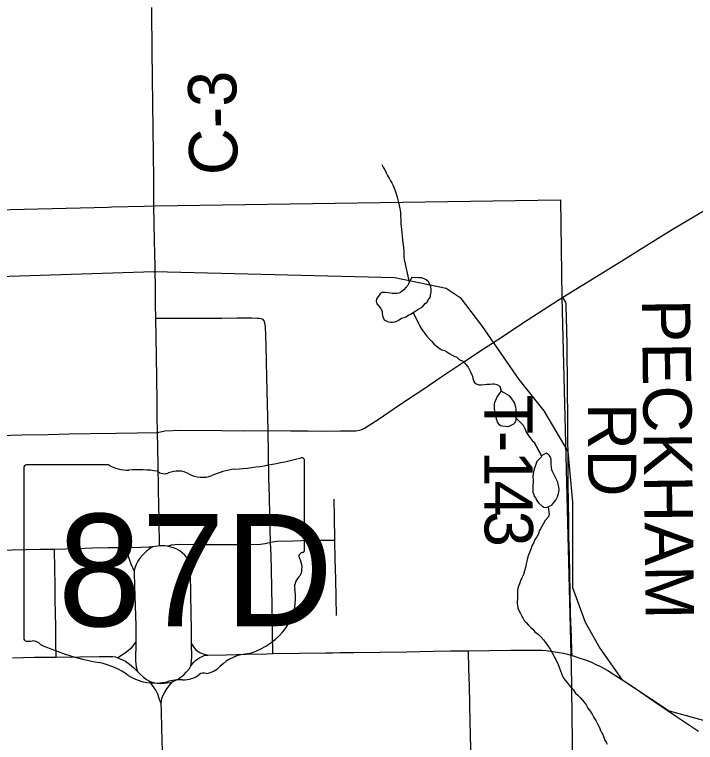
# Model space of a CAD drawing. Extents: x 103424 to 290657, y 38711 to 110967.
# Drawn here: x 160839 to 165088, y 60374 to 64911 of the extents above; entities that cross this region are included whole.
import ezdxf

# ---------------------------------------------------------------- set-up
doc = ezdxf.new("R2010")
doc.units = 0
for name, color, linetype in [('GM_X_City_Street', 7, 'Continuous'), ('GM_X_Corporation', 7, 'Continuous'), ('GM_X_County_Road', 7, 'Continuous'), ('GM_X_County_Road_Text', 7, 'Continuous'), ('GM_X_Minor_Lake', 7, 'Continuous'), ('GM_X_Minor_River', 7, 'Continuous'), ('GM_X_Rail_Line', 7, 'Continuous'), ('GM_X_State_Location', 7, 'Continuous'), ('GM_X_State_Route', 7, 'Continuous'), ('GM_X_State_Shield', 7, 'Continuous'), ('GM_X_Township_Road', 7, 'Continuous'), ('GM_X_Township_Road_Text', 7, 'Continuous')]:
    doc.layers.add(name, color=color, linetype=linetype)

msp = doc.modelspace()

# ---------------------------------------------------------------- linework, layer by layer
at = {"layer": 'GM_X_City_Street'}
for points in [[(161731.1, 62306.2), (161777, 62316.9), (161875.5, 62320.1), (162131.9, 62317.8), (162277.1, 62316.5), (162421.5, 62318), (162560.4, 62317), (162669.7, 62316), (162779.1, 62314.9), (162875.5, 62316), (162971.8, 62317), (162989.9, 62320.1), (163006, 62324.8), (163022.1, 62332.5), (163113.8, 62390.6), (163202.5, 62450.9), (163291.1, 62511.1), (163392.1, 62578.1), (163499.3, 62650.2), (163574.4, 62700.4), (163649.5, 62750.7), (163765.1, 62826.4), (163880.7, 62902.3), (164008.9, 62986.6), (164137, 63070.9), (164260.6, 63148.3)], [(161720.8, 63018.2), (161967.9, 63017.5), (162133, 63018.8), (162226, 63019.5), (162319, 63020.2), (162352.9, 63019.3), (162366.5, 63017.8), (162378.6, 63015.8), (162389.5, 63011.4)], [(162451.3, 60927.5), (162448.8, 61057.2), (162446.1, 61222.2), (162444.2, 61336.9), (162442.3, 61451.5), (162439.5, 61537.2), (162436.7, 61623), (162432.3, 61788), (162429.1, 61905.1), (162426, 62022.1), (162423.7, 62170.1), (162421.5, 62318), (162420, 62400.7), (162418.5, 62483.4), (162414.1, 62648.4), (162411.5, 62749.1), (162408.9, 62849.9), (162404.6, 62966.8), (162403.4, 62976.7), (162401.5, 62987.5), (162396.8, 63001.1), (162389.5, 63011.4)], [(160449, 62278), (160614, 62282.7), (160749.4, 62286.5), (160884.6, 62290.3), (161049.7, 62293.8), (161180.4, 62296.7), (161311.2, 62299.5), (161476.2, 62302.1), (161603.7, 62304.1), (161731.1, 62306.2)], [(162847.6, 61164.1), (162845.3, 61277.7), (162842.9, 61391.4), (162839.8, 61513.4), (162836.8, 61635.4), (162834.9, 61781.4), (162833.5, 61889.3)], [(161960.3, 61607.8), (162013, 61607.4), (162129.9, 61606.7), (162252, 61608.5), (162374.1, 61610.3), (162402.1, 61613.9), (162436.7, 61623)], [(162436.7, 61623), (162475.3, 61627.6), (162577.1, 61631), (162678.8, 61634.3), (162836.8, 61635.4)], [(160461.2, 61566.9), (160571.8, 61570), (160736.9, 61573), (160824.3, 61574.6), (160911.6, 61576.1), (160999.8, 61577.7), (161087.9, 61579.3), (161228.5, 61583.3), (161325.5, 61586.1), (161422.5, 61588.8), (161535.7, 61589.4)], [(161098.6, 60904.2), (161097.8, 61000.5), (161096.9, 61096.9), (161093.8, 61261.9), (161092, 61357.8), (161090.2, 61453.6), (161087.9, 61579.3)], [(161535.7, 61589.4), (161626.7, 61590.6), (161676.3, 61592.3), (161700.6, 61592.1)], [(161586.7, 61443.3), (161566.6, 61484.1), (161555.9, 61515), (161544, 61553.1), (161535.7, 61589.4)], [(161792.7, 61597.2), (161805.7, 61601.9), (161819.1, 61604.8), (161840.7, 61606.6), (161874.4, 61608.6), (161960.3, 61607.8)], [(161932.3, 61477.4), (161939.2, 61509.5), (161947.5, 61547.9), (161955.3, 61584.4), (161960.3, 61607.8)], [(163706.8, 59642.2), (163701.4, 59807.1), (163698.4, 59899.4), (163695.3, 59991.6), (163691.2, 60156.6), (163689, 60247.1), (163686.8, 60337.6), (163682.8, 60502.6), (163680.1, 60613.5), (163677.4, 60724.4), (163674.3, 60835), (163671.2, 60945.6)]]:
    msp.add_lwpolyline(points, dxfattribs=at)
at = {"layer": 'GM_X_Corporation'}
msp.add_lwpolyline([(160200.3, 63681.5), (161423.7, 63710.9), (161447.1, 63711.5), (161648, 63716.6), (161715.5, 63717.6), (164245, 63755), (164253, 63145.7), (164310.7, 60921.1), (164311.2, 60868.6), (164320.2, 60217.4), (164333, 59263.8), (164346.8, 58251.2), (162688.5, 58208.3), (161804.4, 58185.4), (161771.2, 58184.7), (160501.7, 58157)], dxfattribs=at)
at = {"layer": 'GM_X_County_Road'}
msp.add_line((161709.4, 63714.6), (161708.4, 63805.1), dxfattribs=at)
for points in [[(161708.4, 63805.1), (161707.7, 63879.7), (161705.9, 64044.7), (161704.4, 64198.9), (161702.7, 64353.1), (161700.6, 64518.1), (161698.5, 64683.2), (161697.4, 64767.4), (161696.3, 64851.7), (161695.5, 64955.1)], [(161733.1, 62198.3), (161732.9, 62209.1), (161731.1, 62306.2), (161729.8, 62404.9), (161728.6, 62503.6), (161727, 62642.7), (161725.4, 62781.8), (161723.1, 62900), (161720.8, 63018.2), (161719.7, 63100.8), (161718.7, 63183.5), (161716.1, 63342.3), (161713.5, 63501.1), (161711.4, 63607.8), (161709.4, 63714.6)], [(164260.6, 63148.3), (164379.4, 63221.9), (164498.1, 63295.6), (164638.3, 63382.8), (164778.5, 63469.9), (164855.5, 63517.8), (164932.5, 63565.6), (165074.8, 63649.2), (165217.1, 63732.8)], [(161744.6, 61598.4), (161741.4, 61762.1), (161739.6, 61854.5), (161737.9, 61947), (161734.8, 62112.1), (161733.1, 62198.3)]]:
    msp.add_lwpolyline(points, dxfattribs=at)
at = {"layer": 'GM_X_Minor_Lake'}
for points in [[(163317.9, 63271.7), (163302.3, 63243.1), (163292.6, 63222.7), (163282.7, 63212.4), (163268.9, 63195.9), (163257, 63185.6), (163247.1, 63179.3), (163237, 63175), (163225, 63172.8), (163208.8, 63172.4), (163194.7, 63172.1), (163184.5, 63173.9), (163168.3, 63175.6), (163154.1, 63177.3), (163144, 63179.1), (163133.9, 63178.9), (163121.9, 63174.6), (163114, 63162.3), (163104.2, 63147.9), (163098.4, 63137.7), (163096.6, 63125.6), (163099, 63107.4), (163113.5, 63091.6), (163124, 63075.7), (163132.3, 63061.7), (163132.6, 63049.6), (163135, 63033.5), (163145.6, 63007.5), (163166, 62997.8), (163182.3, 62994.1), (163198.5, 62992.5), (163212.6, 62994.8), (163224.6, 62999.1), (163238.6, 63007.5), (163254.5, 63017.9), (163270.6, 63022.3), (163280.6, 63026.6), (163296.6, 63037), (163310.6, 63043.4), (163326.5, 63053.8), (163342.5, 63064.3), (163356.5, 63072.6), (163370.4, 63081), (163384.4, 63089.4), (163402.1, 63110), (163412.1, 63116.2), (163421.8, 63134.6), (163433.6, 63151), (163435.4, 63161.2), (163437.2, 63171.3), (163439, 63183.4), (163438.6, 63199.6), (163436.3, 63213.7), (163429.9, 63229.7), (163421.5, 63245.7), (163407.1, 63257.5), (163394.8, 63263.3), (163378.5, 63269), (163360.8, 63269.8)], [(163360.8, 63269.8), (163317.9, 63271.7)], [(163876.3, 62562.6), (163864.8, 62550.6), (163856.9, 62538.3), (163849.1, 62526), (163843.3, 62515.8), (163835.6, 62497.5), (163831.8, 62483.3), (163832.1, 62469.1), (163832.5, 62451), (163839.5, 62410.7), (163841.7, 62400.7), (163843.9, 62390.6), (163848.2, 62380.6), (163850.4, 62370.6), (163858.7, 62360.7), (163871.1, 62348.8), (163881.2, 62347), (163901.5, 62345.5), (163913.6, 62343.7)], [(163876.3, 62562.6), (163864.8, 62550.6), (163856.9, 62538.3), (163849.1, 62526), (163843.3, 62515.8), (163835.6, 62497.5), (163831.8, 62483.3), (163832.1, 62469.1), (163832.5, 62451), (163839.5, 62410.7), (163841.7, 62400.7), (163843.9, 62390.6), (163848.2, 62380.6), (163850.4, 62370.6), (163858.7, 62360.7), (163871.1, 62348.8), (163881.2, 62347), (163901.5, 62345.5), (163913.6, 62343.7), (163925.7, 62346), (163941.7, 62352.4), (163953.7, 62358.7), (163963.6, 62369), (163969.3, 62385.3), (163969.1, 62395.4), (163968.8, 62409.5), (163968.6, 62421.6), (163968.3, 62435.7), (163968, 62449.9), (163967.7, 62462), (163963.3, 62480.1), (163959, 62490.1), (163952.8, 62500), (163946.5, 62510), (163940.2, 62519.9), (163927.8, 62533.8), (163876.3, 62562.6)], [(163913.6, 62343.7), (163925.7, 62346), (163941.7, 62352.4), (163953.7, 62358.7), (163963.6, 62369), (163969.3, 62385.3), (163969.1, 62395.4), (163968.8, 62409.5), (163968.6, 62421.6), (163968.3, 62435.7), (163968, 62449.9), (163967.7, 62462), (163963.3, 62480.1), (163959, 62490.1), (163952.8, 62500), (163946.5, 62510), (163940.2, 62519.9), (163927.8, 62533.8), (163876.3, 62562.6)], [(164127.7, 62160.6), (164125.9, 62152.4), (164112, 62140), (164098.2, 62125.6), (164079.1, 62070.7), (164075.5, 62048.4), (164073.9, 62030.2), (164074.3, 62010), (164074.7, 61993.8), (164073, 61979.7), (164073.2, 61969.6), (164073.5, 61953.4), (164073.7, 61943.3), (164074, 61933.3), (164078.3, 61919.2), (164080.5, 61909.2), (164090.9, 61897.3), (164093.1, 61887.2), (164101.5, 61875.3), (164109.7, 61865.4), (164128.3, 61847.6), (164142.6, 61839.8), (164152.8, 61838), (164168.9, 61842.4), (164180.8, 61848.7), (164190.9, 61853), (164204.7, 61869.5), (164216.5, 61883.8), (164222.3, 61896.1), (164228.1, 61908.3), (164231.9, 61918.5), (164235.7, 61932.7), (164237.2, 61953), (164235, 61965), (164230.5, 61983.1), (164228.3, 61995.2), (164217.7, 62017.1), (164207.2, 62037.1), (164196.5, 62063.1), (164192.2, 62073.1), (164189.9, 62087.2), (164187.5, 62107.3), (164186.8, 62137.6), (164184.6, 62147.7), (164174.1, 62163.6), (164161.8, 62173.4), (164155.7, 62177.3), (164127.7, 62160.6)], [(164127.7, 62160.6), (164125.9, 62152.4), (164112, 62140), (164098.2, 62125.6), (164079.1, 62070.7), (164075.5, 62048.4), (164073.9, 62030.2), (164074.3, 62010), (164074.7, 61993.8), (164073, 61979.7), (164073.2, 61969.6), (164073.5, 61953.4), (164073.7, 61943.3), (164074, 61933.3), (164078.3, 61919.2), (164080.5, 61909.2), (164090.9, 61897.3), (164093.1, 61887.2), (164101.5, 61875.3), (164109.7, 61865.4), (164128.3, 61847.6), (164142.6, 61839.8), (164152.8, 61838), (164168.9, 61842.4)], [(164168.9, 61842.4), (164180.8, 61848.7), (164190.9, 61853), (164204.7, 61869.5), (164216.5, 61883.8), (164222.3, 61896.1), (164228.1, 61908.3), (164231.9, 61918.5), (164235.7, 61932.7), (164237.2, 61953), (164235, 61965), (164230.5, 61983.1), (164228.3, 61995.2), (164217.7, 62017.1), (164207.2, 62037.1), (164196.5, 62063.1), (164192.2, 62073.1), (164189.9, 62087.2), (164187.5, 62107.3), (164186.8, 62137.6), (164184.6, 62147.7), (164174.1, 62163.6), (164161.8, 62173.4), (164155.7, 62177.3), (164127.7, 62160.6)]]:
    msp.add_lwpolyline(points, dxfattribs=at)
at = {"layer": 'GM_X_Minor_River'}
for points in [[(163131.8, 63975.7), (163135.3, 63968.4), (163141.6, 63956.4), (163150, 63942.4), (163158.4, 63924.4), (163166.9, 63908.5), (163177.4, 63890.5), (163185.8, 63874.6), (163194.1, 63862.6), (163200.5, 63848.6), (163204.8, 63834.6), (163213.4, 63812.6), (163219.9, 63792.5), (163226.4, 63772.5), (163230.7, 63756.4), (163235.2, 63738.3), (163239.6, 63720.3), (163244, 63702.2), (163246.6, 63678), (163247, 63655.8), (163249.6, 63631.6), (163250.1, 63605.4), (163252.9, 63571.1), (163255.3, 63551), (163257.8, 63528.8), (163260.3, 63506.7), (163262.6, 63492.6), (163265.4, 63456.3), (163267.9, 63436.2), (163268.2, 63420), (163268.6, 63401.9), (163271.1, 63381.7), (163273.4, 63367.6), (163275.5, 63363.6), (163275.5, 63361.6), (163275.7, 63355.6), (163302.3, 63243.1)], [(163326.5, 63053.8), (163370.9, 62963.9), (163381.3, 62948), (163389.6, 62938.1), (163395.9, 62928.1), (163404.2, 62916.2), (163412.5, 62906.3), (163429.1, 62888.4), (163441.5, 62874.6), (163456, 62858.7), (163470.4, 62844.9), (163488.9, 62831.2), (163505.3, 62821.5), (163521.5, 62817.8), (163535.9, 62808), (163554.3, 62796.3), (163574.8, 62786.6), (163587, 62778.8), (163597.2, 62777), (163609.6, 62765.2), (163621.9, 62757.3), (163634.1, 62751.6), (163646.5, 62739.7), (163656.9, 62727.8), (163669.3, 62711.9), (163677.7, 62696), (163686.2, 62680), (163692.5, 62666), (163696.8, 62656), (163699.1, 62641.9), (163705.6, 62623.9), (163713.9, 62611.9), (163738.4, 62602.4), (163752.5, 62602.7), (163770.6, 62605.1), (163786.7, 62607.5), (163796.8, 62607.7), (163807, 62607.9), (163821.1, 62608.2), (163831.2, 62608.4), (163847.4, 62604.8), (163863.8, 62597), (163867.9, 62595.1), (163876.3, 62562.6)], [(163969.1, 62395.4), (164012.5, 62351.9), (164018.9, 62337.9), (164025.2, 62325.9), (164033.7, 62303.9), (164042, 62294), (164048.3, 62282), (164056.6, 62272.1), (164069.1, 62256.2), (164081.5, 62244.4), (164127.7, 62160.6), (164081.5, 62244.4)], [(164168.9, 61842.4), (164173.9, 61794.1), (164168.2, 61777.8), (164150.5, 61757.2), (164121.2, 61706.1), (164113.4, 61691.8), (164107.8, 61673.5), (164098.1, 61655.1), (164086.3, 61638.7), (164078.6, 61620.4), (164068.8, 61604), (164063.2, 61583.7), (164053.6, 61561.3), (164045.9, 61542.9), (164040.2, 61522.6), (164034.6, 61504.3), (164030.9, 61486.1), (164027.3, 61463.8), (164021.7, 61443.5), (164014.1, 61421.1), (164004.4, 61400.7), (163996.8, 61380.4), (163989.1, 61362), (163983.3, 61347.8), (163979.6, 61333.5), (163977.9, 61319.4), (163978.1, 61309.3), (163978.3, 61299.2), (163976.5, 61287), (163976.9, 61268.9), (163975.3, 61250.7), (163975.5, 61238.6), (163977.8, 61228.5), (163980.2, 61212.4), (163984.4, 61202.4), (163990.8, 61188.4), (163995.1, 61176.4), (164001.4, 61164.4), (164009.8, 61150.5), (164018.2, 61134.5), (164030.6, 61120.6), (164045.1, 61104.8), (164059.5, 61091), (164073.9, 61079.2), (164086.4, 61063.3), (164106.9, 61047.6), (164123.5, 61031.8), (164140, 61014), (164152.5, 60996.1), (164167.1, 60976.2), (164181.7, 60954.3), (164194.3, 60932.4), (164223.7, 60878.5), (164230.2, 60860.5), (164238.8, 60836.4), (164245.2, 60820.4), (164251.6, 60802.4), (164258, 60786.3), (164266.4, 60772.4), (164274.7, 60762.5), (164283, 60750.5), (164291.3, 60740.6), (164301.7, 60728.7), (164314.1, 60714.9), (164326.5, 60701), (164339.1, 60681.1), (164355.6, 60667.3), (164368, 60653.5), (164380.4, 60639.6), (164392.9, 60623.7), (164405.3, 60607.8), (164415.9, 60587.8), (164430.4, 60568), (164442.9, 60550.1), (164453.5, 60530.1), (164466, 60510.2), (164476.6, 60490.2), (164489.2, 60466.3), (164495.6, 60448.2), (164501.9, 60436.3), (164508.2, 60426.3), (164514.6, 60410.3), (164518.9, 60400.3), (164523.2, 60388.3), (164529.5, 60376.3), (164535.9, 60362.3)]]:
    msp.add_lwpolyline(points, dxfattribs=at)
at = {"layer": 'GM_X_Rail_Line'}
msp.add_lwpolyline([(160415.4, 63267.2), (161709.6, 63308.7), (163212.6, 63271.3), (163532.3, 63204.9), (163619.5, 63146.7), (163752.3, 62972.3), (163984.8, 62635.9), (164142.6, 62440.7), (164292.1, 62187.3), (164321.1, 61871.7), (164321.1, 61340), (164400, 61124.1), (164491.4, 60962.1), (164628.4, 60766.9), (164923.1, 60571.7), (165172.3, 60501.1)], dxfattribs=at)
at = {"layer": 'GM_X_State_Route'}
for points in [[(161744.6, 61598.4), (161732.9, 61597.6), (161717.5, 61595.6), (161700.6, 61592.1), (161681.7, 61580.4), (161663.5, 61565.2), (161654.1, 61556.8), (161641.1, 61544.4), (161624.2, 61523.8), (161609.5, 61502.9), (161597.5, 61483), (161589.2, 61459.4), (161586.7, 61443.3), (161585.5, 61435.9), (161587, 61347), (161591.9, 61224.8), (161596.9, 61102.5), (161596.9, 61000.9), (161595, 60881.6), (161598.7, 60845.8), (161605.5, 60816.6)], [(161940.2, 60851), (161943.8, 60879.9), (161945.5, 60907.2), (161944.3, 60987.6), (161943, 61081.2), (161941.8, 61174.8), (161939.6, 61300.5), (161937.4, 61426.1), (161936.2, 61450.7), (161932.3, 61477.4), (161926.9, 61495.8), (161921, 61511.6), (161911.6, 61528), (161901.1, 61540.9), (161888.2, 61553.2), (161869.9, 61568.4), (161851.2, 61579.1), (161830.7, 61586.6), (161813.9, 61591.4), (161792.7, 61597.2), (161777, 61598.9), (161744.6, 61598.4)], [(161596.9, 61000.9), (161582.5, 60981.2), (161564.4, 60960.2), (161539.1, 60938.1), (161506, 60915), (161484.5, 60900.7)], [(161944.3, 60987.6), (161960.1, 60962.6), (161970.8, 60950.8), (161984, 60940.3), (161996.3, 60933.7), (162009.9, 60928.5), (162023.6, 60924.9), (162045.8, 60917.7)], [(162822.7, 60932.9), (162869.1, 60933.6), (162956.8, 60934.9), (163121.5, 60936.2), (163286.5, 60939), (163451.5, 60941.9), (163561.4, 60943.7), (163671.2, 60945.6), (163803.1, 60947), (163935, 60948.3), (164051.9, 60949.8), (164104.9, 60949.2), (164130.8, 60948), (164157.2, 60945.8), (164185.1, 60942.7), (164212, 60938.9), (164237.3, 60934.6), (164264.2, 60929.2), (164289.8, 60923), (164317.4, 60916.1)], [(160826.9, 60900.1), (160964.4, 60904.2), (161098.6, 60904.2), (161247.5, 60907.9), (161367.2, 60909), (161420.1, 60909.8), (161451.8, 60909), (161468.9, 60906.9), (161484.5, 60900.7), (161503.2, 60893.2), (161531.7, 60879.7), (161557.5, 60861.6), (161581.5, 60841.2), (161605.5, 60816.6)], [(161940.2, 60851), (161956.9, 60872.5), (161967.9, 60884.8), (161982.5, 60895.6), (161994.6, 60903), (162006.4, 60908.3), (162023.1, 60914.8), (162045.8, 60917.7)], [(162045.8, 60917.7), (162159.5, 60920.6), (162286.9, 60923.6), (162414.3, 60926.7), (162451.3, 60927.5), (162616.3, 60929.9), (162781.4, 60932.3), (162822.7, 60932.9)], [(164317.4, 60916.1), (164343.6, 60907.8), (164367.1, 60899.8), (164392.8, 60891), (164417.9, 60881.5), (164443, 60871.6), (164466.8, 60860.3), (164491.4, 60848.4), (164540.2, 60821.5), (164583.5, 60795.9), (164692.1, 60723.8), (164828.8, 60631.4), (164899.2, 60583.9), (164969.5, 60536.4), (165106, 60443.5)], [(161680.6, 60756), (161704, 60747.2), (161727.1, 60743.1), (161749.5, 60741.8), (161791.8, 60744.2), (161807.6, 60747.3), (161824.5, 60751.9), (161841.3, 60759), (161860.3, 60769), (161878.8, 60782), (161894.6, 60794.7), (161910.8, 60811.4), (161930.1, 60835.1), (161940.2, 60851)], [(161605.5, 60816.6), (161625.2, 60797.2), (161643.2, 60781.4), (161661.8, 60766.6), (161680.6, 60756)], [(161753.5, 60613.7), (161742.6, 60648), (161733.1, 60674.7), (161720, 60699.5), (161710.9, 60713.5), (161680.6, 60756)], [(161753.5, 60613.7), (161759.1, 60647.7), (161766.7, 60668.4), (161776.4, 60687.8), (161790.1, 60707.3), (161804.1, 60727.1), (161824.5, 60751.9)], [(161784.8, 59525.7), (161782.9, 59592.3), (161781.2, 59651), (161779.4, 59717.8), (161777.9, 59772.6), (161775.7, 59826.2), (161773.7, 59922.2), (161771.2, 60015.7), (161769.6, 60073.1), (161767.3, 60157.2), (161765.5, 60222.1), (161762.9, 60314.2), (161760.8, 60391.7), (161758.9, 60459.1), (161755.3, 60571.3), (161753.5, 60613.7)]]:
    msp.add_lwpolyline(points, dxfattribs=at)
at = {"layer": 'GM_X_State_Shield'}
for p, q in [((162648.3, 61574.8), (162648.3, 62131)), ((160897.3, 62086.4), (160897.3, 61023.1)), ((161427.3, 62104.7), (160914.5, 62104.7)), ((162648.2, 61574.9), (162648.3, 61574.8))]:
    msp.add_line(p, q, dxfattribs=at)
for centre, major_axis, start_param, end_param in [((162024.6, 63554.2), (1857, 0), 4.814394, 5.042369), ((162628.9, 62133.3), (19.5, 0), 6.141152, 7.989035), ((160917.3, 62088.6), (20.3, 0), 1.712693, 3.28349), ((161549.4, 62228.1), (196.8, 0), 4.042523, 4.731795), ((161614.7, 61507.7), (706.4, 0), 1.404758, 1.657858), ((161858.4, 61971.2), (118, 0), 0.950623, 2.079405), ((162261.4, 61779.9), (373.6, 0), 1.699011, 2.107814), ((161775, 62094.1), (56.8, 0), 3.836095, 5.185415), ((162010.7, 62139.8), (142, 0), 4.081561, 5.145723), ((162627.5, 61572.7), (20.9, 0), 5.05454, 6.418171), ((162643.8, 61534), (30.2, 0), 1.883978, 3.671073), ((162451.9, 61463.7), (181.1, 0), 5.934695, 6.695948), ((162718.2, 61342.1), (131.8, 0), 2.387724, 3.262537), ((162128.6, 61271.3), (464.5, 0), 5.101752, 6.440018), ((160917.5, 61020.8), (20.5, 0), 3.00124, 4.508301), ((160920.6, 61129.6), (156.2, 0), 4.665946, 4.897461), ((160952.6, 60961.8), (56.3, 0), 0.519207, 1.627899), ((161663.6, 61917.1), (1341, 0), 4.195997, 4.488961), ((162324.5, 60724.6), (254.4, 0), 1.647645, 2.488434), ((161263.8, 60545.5), (419.6, 0), 0.823519, 1.323587), ((162002.2, 60920.1), (150.1, 0), 4.937069, 5.64225), ((162019.2, 60773.9), (39.9, 0), 1.147584, 2.315152), ((161717.6, 60956.5), (266.2, 0), 4.026481, 4.996735), ((161871.4, 60588.9), (218.8, 0), 1.495662, 1.94098), ((161890.9, 60876.9), (141.9, 0), 4.691044, 5.507374)]:
    msp.add_ellipse(centre, major_axis=major_axis, ratio=0.8, start_param=start_param, end_param=end_param, dxfattribs=at)
at = {"layer": 'GM_X_Township_Road'}
msp.add_lwpolyline([(164317.4, 60916.1), (164316.7, 60942.1), (164313.4, 61034.3), (164310.1, 61126.5), (164308.2, 61179.9), (164306.3, 61305.3), (164304.5, 61430.7), (164301.3, 61541.6), (164298.2, 61652.6), (164296.8, 61751.7), (164295.1, 61868.7), (164293.3, 61985.7), (164292.4, 62150.7), (164291.7, 62277.1), (164291, 62403.4), (164289.5, 62568.5), (164288.6, 62667), (164287.7, 62765.6), (164286.9, 62854.9), (164286.1, 62944.3), (164281.8, 63095.4), (164280, 63107.5), (164276.2, 63119.1), (164271.1, 63130.4), (164260.6, 63148.3)], dxfattribs=at)

# ---------------------------------------------------------------- texts
at = {"layer": 'GM_X_County_Road_Text'}
msp.add_text('C-3', height=301.87, rotation=90.9075, dxfattribs=at).set_placement((162232.2, 63912.1))
at = {"layer": 'GM_X_State_Location'}
for s in ['s', 'r']:
    msp.add_text(s, height=1.01, dxfattribs=at).set_placement((161753.1, 61484.1))
msp.add_text('87D', height=1.01, rotation=0, dxfattribs=at).set_placement((161366.9, 61410.9))
at = {"layer": 'GM_X_State_Shield'}
msp.add_text('87D', height=700.44, dxfattribs=at).set_placement((161109.3, 61098.1))
at = {"layer": 'GM_X_Township_Road_Text'}
for s, height, rotation, p in [('PECKHAM', 301.87, 270.7005, (164753.2, 63135.6)), ('T', 301.9, 270, (163769.5, 62542.8)), ('RD', 301.87, 270, (164416.5, 62489.6)), ('-', 301.9, 270.0071, (163769.5, 62316.9)), ('1', 301.9, 270.0502, (163769.5, 62192.7)), ('4', 301.9, 270.2169, (163769.7, 62005.8)), ('3', 301.9, 270.9761, (163770.5, 61815.5))]:
    msp.add_text(s, height=height, rotation=rotation, dxfattribs=at).set_placement(p)

doc.saveas('drawing.dxf')
